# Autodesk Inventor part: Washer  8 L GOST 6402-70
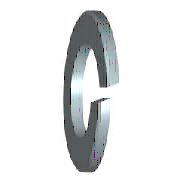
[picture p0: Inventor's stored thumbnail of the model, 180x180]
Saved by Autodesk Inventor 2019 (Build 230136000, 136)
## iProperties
Created: 2018-01
Part Number: Washer  8 L GOST 6402-70
Material: Steel, Mild
Description: Lock washers
Document SubType Name: Modeling
Standard: GOST 6402-70
Designer: m.vorobev
Standards Organization: GOST
Language: en-US
Size Designation: 8 L
Categories: <MemberInstance><Categories><Category DisplayName="Fasteners" InternalName="e4da775c-781d-43d5-af7c-5136215cf5a6" Mnemonic="FSTN"><Category DisplayName="Washers
Density: 7.85 g/cm^3
Appearance: Semi-Polished
IsCustomPart: 0
Author: m.vorobev
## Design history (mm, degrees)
sketch "Sketch1"
  geometry: C1 r 6.1 at (0, 0); C2 r 4.1 at (0, 0); 1 further point
  constraints: 2 centre point, 2 coincident
  dimensions: "d0" = 8.2 diameter of C2 (= SD1); "d1" = 12.2 diameter of C1 (= SD2)
extrude "Body" new body sketch "Sketch1" distance "d2" = 1.6 (= SD); taper "d3" = 0 deg
sketch "Sketch2"
  geometry: L1 (0, -4.1)-(0, 4.1) reference; L2 (1.6, 6.1)-(1.6, -6.1) reference; L3 (-1.2, 0)-(7.2, 0) reference; L4 (0, -0.32)-(1.6, 0.262); L5 (0, 0.32)-(1.6, 0.902)
  constraints: 4 end point, 4 point on line, 1 parallel
  dimensions: "d4" = 0.32 distance from line of L3 L4.start (= 0.2 x SD); "d5" = 0.32 distance from line of L3 L5.start (= 0.2 x SD); "d6" = 70 deg angle of L2 L4 (= FAWI)
extrude "Cut" cut sketch "Sketch2" stored distance "d7" = 1.6 (= SD); taper "d8" = 0 deg
workaxis "Work Axis1"
workplane "Work Plane1"
body "Solid1"
other parameters: "SD1" = 8.2 [user parameter; used in 1 equation term], "SD2" = 12.2 [user parameter; used in 1 equation term], "SD" = 1.6 [user parameter; used in 4 equation terms], "FAWI" = 70 deg [user parameter; used in 1 equation term], "d9" = 0, "d10" = 0, "d11" = 0, "d12" = 0, "NND" = 8 [user parameter]
